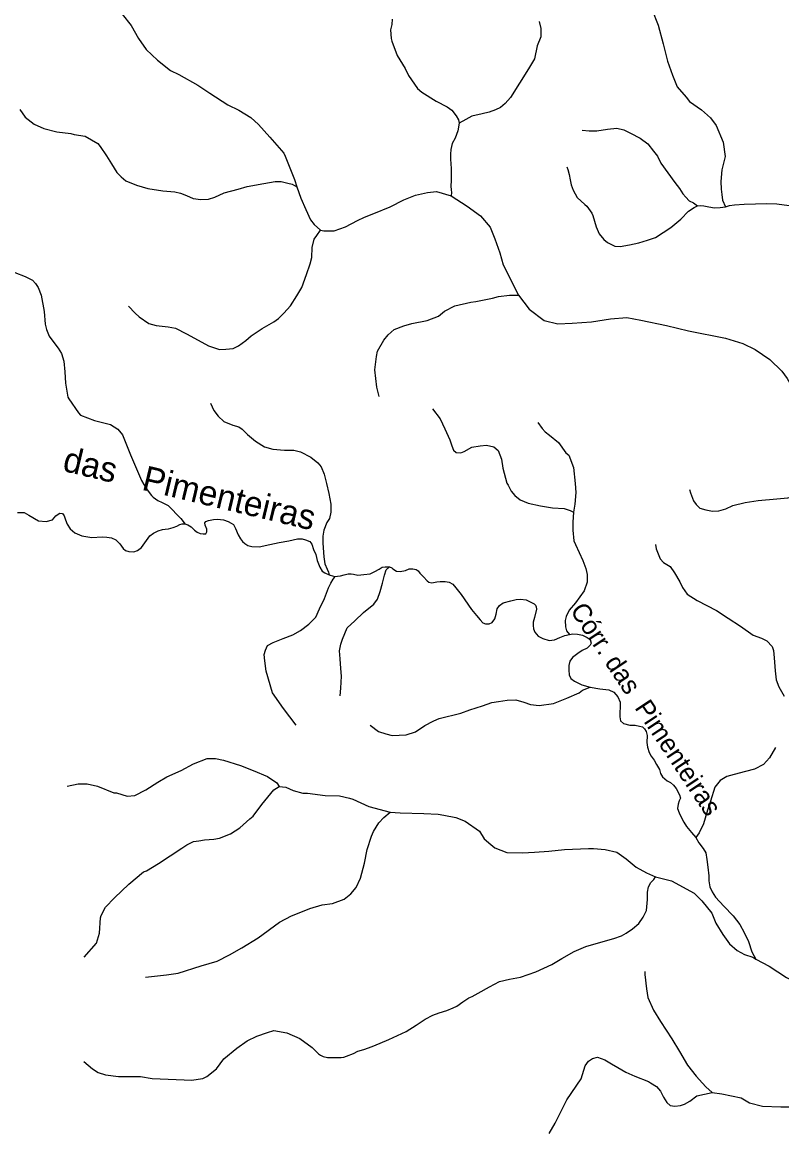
# Model space of a CAD drawing. Extents: x 436.3 to 500.4, y 8231 to 8286.4.
# Drawn here: x 478.01 to 484.1, y 8252.95 to 8261.84 of the extents above; entities that cross this region are included whole.
import ezdxf
from ezdxf.enums import TextEntityAlignment as Align

# ---------------------------------------------------------------- set-up
doc = ezdxf.new("R2010")
doc.units = 0
doc.header["$LTSCALE"] = 0.08
doc.linetypes.add('LONG_DASHED', pattern=[7.5, 6, -1.5])
doc.layers.add('61', color=7, linetype='Continuous')
doc.layers.add('9', color=7, linetype='LONG_DASHED', lineweight=25)

msp = doc.modelspace()

# ---------------------------------------------------------------- linework, layer by layer
at = {"layer": '9'}
for points in [[(478.8118, 8261.9018), (478.8826, 8261.8102), (478.9428, 8261.708), (479.003, 8261.6199), (479.0951, 8261.5319), (479.1978, 8261.4509), (479.2651, 8261.4193), (479.4186, 8261.333), (479.5142, 8261.2696), (479.6593, 8261.1746), (479.7478, 8261.1323), (479.8435, 8261.0724), (479.9036, 8261.0161), (479.9957, 8260.914), (480.109, 8260.7871), (480.1196, 8260.7624), (480.194, 8260.5757), (480.2117, 8260.5158)], [(483.0603, 8261.9419), (483.1111, 8261.8132), (483.1517, 8261.664), (483.1856, 8261.5251), (483.2262, 8261.4133), (483.2635, 8261.3185), (483.3357, 8261.2354), (483.3629, 8261.2015), (483.458, 8261.1338), (483.5294, 8261.0694), (483.577, 8261.0085), (483.6313, 8260.8763), (483.6482, 8260.7596), (483.6208, 8260.6545), (483.614, 8260.5596), (483.6173, 8260.4989), (483.6207, 8260.4549), (483.6275, 8260.4109), (483.6512, 8260.3567)], [(480.9782, 8261.8607), (480.9734, 8261.8184), (480.9623, 8261.7766), (480.9677, 8261.7071), (480.9733, 8261.6848), (481.0179, 8261.5706), (481.0821, 8261.4649), (481.1072, 8261.4093), (481.1798, 8261.3063), (481.2161, 8261.2757), (481.3305, 8261.2033), (481.417, 8261.1588), (481.4568, 8261.1321), (481.4903, 8261.0874), (481.5094, 8261.0546), (481.5132, 8261.0267)], [(482.1555, 8261.8443), (482.1702, 8261.7858), (482.1701, 8261.7201), (482.1407, 8261.647), (482.1186, 8261.5446), (482.0709, 8261.4643), (481.9274, 8261.2333), (481.8834, 8261.1858), (481.8466, 8261.1529), (481.8063, 8261.1346), (481.7549, 8261.1164), (481.6999, 8261.1017), (481.6156, 8261.0834), (481.5679, 8261.0579), (481.5132, 8261.0267)], [(477.9899, 8261.1367), (478.0328, 8261.0753), (478.1053, 8261.0198), (478.1815, 8260.9844), (478.2862, 8260.9586), (478.3981, 8260.9444), (478.4267, 8260.9374), (478.5148, 8260.9234), (478.6147, 8260.8643), (478.6338, 8260.8406), (478.6862, 8260.7649), (478.7243, 8260.7011), (478.7696, 8260.6325), (478.8036, 8260.5959), (478.8417, 8260.5652), (478.925, 8260.5298), (479.0178, 8260.5039), (479.1369, 8260.4851), (479.2343, 8260.4757), (479.278, 8260.4656), (479.328, 8260.4467), (479.3803, 8260.4231), (479.4422, 8260.4161), (479.504, 8260.4184), (479.554, 8260.435), (479.6301, 8260.4682), (479.7418, 8260.4968), (479.8132, 8260.5205), (479.9467, 8260.5448), (480.0394, 8260.559), (480.087, 8260.5591), (480.1393, 8260.5472), (480.175, 8260.5378), (480.2117, 8260.5158)], [(481.5132, 8261.0267), (481.5038, 8260.965), (481.4813, 8260.9072), (481.4588, 8260.8641), (481.4475, 8260.8157), (481.4456, 8260.7801), (481.4456, 8260.739), (481.4513, 8260.6644), (481.4491, 8260.5664), (481.4472, 8260.5217), (481.4492, 8260.4917), (481.4529, 8260.4712), (481.4492, 8260.445)], [(482.5003, 8260.9702), (482.5561, 8260.9654), (482.6192, 8260.9653), (482.7057, 8260.9793), (482.7805, 8260.9863), (482.8343, 8260.9747), (482.8881, 8260.9467), (482.9652, 8260.907), (483.0283, 8260.8605), (483.0727, 8260.8022), (483.1054, 8260.7626), (483.1334, 8260.7067), (483.1871, 8260.6298), (483.2432, 8260.5506), (483.2812, 8260.5037), (483.3093, 8260.4618), (483.3325, 8260.434), (483.3607, 8260.4058), (483.3935, 8260.3896), (483.4256, 8260.3655)], [(482.3786, 8260.6773), (482.3854, 8260.657), (482.3956, 8260.6163), (482.4058, 8260.5723), (482.4126, 8260.5316), (482.4296, 8260.491), (482.4602, 8260.43), (482.5214, 8260.3758), (482.5384, 8260.3622), (482.5792, 8260.3047), (482.586, 8260.2877), (482.6132, 8260.1962), (482.637, 8260.1387), (482.6744, 8260.0947), (482.705, 8260.071), (482.7628, 8260.0404), (482.807, 8260.037), (482.8818, 8260.0506), (482.9565, 8260.0675), (483.0245, 8260.0879), (483.0891, 8260.1115), (483.2114, 8260.1894), (483.293, 8260.2572), (483.3542, 8260.3215), (483.3985, 8260.352), (483.4256, 8260.3655)], [(480.2117, 8260.5158), (480.2449, 8260.4253), (480.2839, 8260.3337), (480.3229, 8260.2526), (480.3512, 8260.2139), (480.4009, 8260.1693)], [(480.4009, 8260.1693), (480.4295, 8260.1647), (480.5108, 8260.1647), (480.6029, 8260.1965), (480.6983, 8260.2458), (480.7549, 8260.2741), (480.8292, 8260.3022), (480.96, 8260.3551), (481.0696, 8260.4115), (481.1651, 8260.4503), (481.2606, 8260.4715), (481.3313, 8260.4785), (481.4492, 8260.445)], [(481.4492, 8260.445), (481.5788, 8260.3622), (481.6849, 8260.2847), (481.7627, 8260.1931), (481.7996, 8260.1006), (481.8416, 8259.9871), (481.8676, 8259.8904), (481.9907, 8259.6476)], [(483.4256, 8260.3655), (483.4481, 8260.3678), (483.4781, 8260.3651), (483.5176, 8260.3557), (483.5639, 8260.3489), (483.6088, 8260.3502), (483.6512, 8260.3567)], [(483.6512, 8260.3567), (483.6838, 8260.3666), (483.7219, 8260.372), (483.7996, 8260.3788), (483.9833, 8260.3828), (484.0638, 8260.3802), (484.1606, 8260.3667)], [(478.8615, 8259.56), (478.916, 8259.5022), (478.9472, 8259.4752), (479.025, 8259.4211), (479.0833, 8259.4057), (479.1805, 8259.3943), (479.2387, 8259.3828), (479.3281, 8259.3365), (479.4215, 8259.2863), (479.5032, 8259.2401), (479.5926, 8259.2131), (479.643, 8259.2132), (479.7013, 8259.221), (479.7439, 8259.2404), (479.8021, 8259.2829), (479.8448, 8259.3215), (479.934, 8259.3796), (480.0271, 8259.4338), (480.0659, 8259.4609), (480.1084, 8259.5034), (480.1627, 8259.5614), (480.213, 8259.6425), (480.2517, 8259.7082), (480.2904, 8259.8126), (480.3181, 8259.8994), (480.3335, 8259.9497), (480.3354, 8260.0294), (480.3517, 8260.0957), (480.3722, 8260.1273), (480.4009, 8260.1693)], [(477.9497, 8259.8287), (478.034, 8259.7967), (478.0923, 8259.7678), (478.115, 8259.7421), (478.1378, 8259.7099), (478.1605, 8259.6488), (478.1866, 8259.5169), (478.1937, 8259.4148), (478.2035, 8259.373), (478.2262, 8259.3183), (478.2619, 8259.2669), (478.2977, 8259.2219), (478.3236, 8259.18), (478.3432, 8259.1189), (478.3499, 8259.0321), (478.3565, 8258.9419), (478.3762, 8258.8294), (478.3827, 8258.8165), (478.4607, 8258.704), (478.4769, 8258.6846), (478.5904, 8258.643), (478.7167, 8258.611), (478.7751, 8258.5724), (478.814, 8258.5274), (478.8773, 8258.3678), (478.9652, 8258.162), (479.0042, 8258.0977), (479.0465, 8258.0398), (479.06, 8258.0262), (479.0963, 8258.0017), (479.1328, 8257.9837), (479.1535, 8257.9746), (479.1795, 8257.9605), (479.2133, 8257.9283), (479.2483, 8257.8884), (479.2822, 8257.8549), (479.3017, 8257.8331), (479.3149, 8257.8127)], [(480.8723, 8258.836), (480.8549, 8258.9095), (480.8372, 8259.0478), (480.85, 8259.1558), (480.8586, 8259.1991), (480.9106, 8259.2855), (480.9452, 8259.3288), (480.9928, 8259.372), (481.0709, 8259.4023), (481.136, 8259.4196), (481.2574, 8259.4455), (481.3484, 8259.4801), (481.3962, 8259.519), (481.4785, 8259.5622), (481.6086, 8259.5926), (481.6476, 8259.5969), (481.782, 8259.6228), (481.8298, 8259.6357), (481.9169, 8259.6486), (481.9907, 8259.6476)], [(481.9907, 8259.6476), (482.0749, 8259.5359), (482.1958, 8259.4436), (482.3057, 8259.4173), (482.4206, 8259.4226), (482.576, 8259.4332), (482.728, 8259.4578), (482.8587, 8259.4684), (482.9719, 8259.4473), (483.1771, 8259.405), (483.354, 8259.3628), (483.6512, 8259.3031), (483.7893, 8259.2609), (483.8886, 8259.2118), (484.0056, 8259.1308), (484.1034, 8259.0383), (484.1461, 8258.9784), (484.2137, 8258.8624), (484.2635, 8258.7639), (484.349, 8258.5669), (484.3882, 8258.4578), (484.4632, 8258.2467), (484.531, 8258.0902), (484.5562, 8258.0303)], [(479.521, 8258.7805), (479.5462, 8258.7232), (479.5824, 8258.6767), (479.6257, 8258.6336), (479.6978, 8258.6051), (479.7483, 8258.5908), (479.7736, 8258.5729), (479.8169, 8258.5299), (479.8818, 8258.4762), (479.954, 8258.4297), (480.0188, 8258.4119), (480.1125, 8258.4048), (480.1881, 8258.4048), (480.2421, 8258.3905), (480.325, 8258.3476), (480.3818, 8258.3014), (480.4072, 8258.2715), (480.4305, 8258.2118), (480.4492, 8258.1381), (480.4679, 8258.0576), (480.4843, 8257.9703), (480.4844, 8257.9058), (480.4738, 8257.8567), (480.4535, 8257.8241), (480.429, 8257.7631), (480.421, 8257.7142), (480.4212, 8257.6571), (480.4296, 8257.5472), (480.4372, 8257.4925), (480.4552, 8257.4488), (480.4653, 8257.4249), (480.4718, 8257.4051)], [(481.3004, 8258.7355), (481.3624, 8258.6569), (481.4004, 8258.5747), (481.4384, 8258.4858), (481.4557, 8258.4378), (481.4695, 8258.4036), (481.4901, 8258.3866), (481.5279, 8258.3831), (481.5554, 8258.3934), (481.6172, 8258.4277), (481.6823, 8258.4379), (481.7339, 8258.4448), (481.7923, 8258.4311), (481.8267, 8258.4003), (481.8543, 8258.3319), (481.8648, 8258.26), (481.896, 8258.1402), (481.9063, 8258.1232), (481.9305, 8258.0752), (481.9615, 8258.041), (482.0028, 8258.0068), (482.0681, 8257.9794), (482.1677, 8257.9589), (482.264, 8257.9419), (482.3567, 8257.935), (482.4049, 8257.9214), (482.4303, 8257.9061)], [(482.1459, 8258.6265), (482.1804, 8258.5787), (482.2045, 8258.5512), (482.2389, 8258.5239), (482.3112, 8258.4657), (482.3697, 8258.3837), (482.3939, 8258.3631), (482.4319, 8258.2639), (482.4459, 8258.1373), (482.4495, 8258.0655), (482.443, 8257.9713), (482.4303, 8257.9061)], [(483.3616, 8258.0878), (483.37, 8258.0627), (483.3954, 8257.9985), (483.4151, 8257.9679), (483.446, 8257.94), (483.4937, 8257.9261), (483.5469, 8257.9149), (483.5975, 8257.9178), (483.6535, 8257.9346), (483.7094, 8257.9597), (483.8075, 8257.9849), (483.914, 8258.0017), (484.0625, 8258.013), (484.1523, 8258.0215), (484.228, 8258.0439), (484.2869, 8258.0607), (484.3345, 8258.0719), (484.3878, 8258.0748), (484.4299, 8258.0748), (484.472, 8258.0665), (484.5085, 8258.0554), (484.5562, 8258.0303)], [(477.9721, 8257.9042), (478.0262, 8257.9043), (478.0624, 8257.882), (478.1391, 8257.8373), (478.2023, 8257.8329), (478.2518, 8257.8464), (478.2787, 8257.8777), (478.2967, 8257.8912), (478.3107, 8257.8989), (478.3318, 8257.8967), (478.3459, 8257.8781), (478.3553, 8257.8456), (478.3693, 8257.8108), (478.3951, 8257.7738), (478.4326, 8257.7414), (478.4862, 8257.7182), (478.568, 8257.7045), (478.6519, 8257.7091), (478.6869, 8257.7069), (478.7243, 8257.6999), (478.7616, 8257.6837), (478.7921, 8257.6536), (478.8202, 8257.6166), (478.8365, 8257.598), (478.8646, 8257.5911), (478.9042, 8257.5888), (478.9345, 8257.6004), (478.9671, 8257.6237), (478.9927, 8257.6609), (479.034, 8257.7164), (479.0622, 8257.7382), (479.1005, 8257.7562), (479.1344, 8257.7675), (479.157, 8257.7699), (479.184, 8257.7721), (479.2202, 8257.7834), (479.2495, 8257.7946), (479.2743, 8257.8081), (479.2924, 8257.8127), (479.3149, 8257.8127)], [(482.4303, 8257.9061), (482.4262, 8257.8275), (482.4263, 8257.7625), (482.4335, 8257.6769), (482.4472, 8257.6461), (482.5059, 8257.5194), (482.5302, 8257.4544), (482.5406, 8257.4065), (482.5407, 8257.3449), (482.5168, 8257.2764), (482.4483, 8257.1805), (482.3969, 8257.12), (482.3729, 8257.0685), (482.3661, 8257.0377), (482.3662, 8256.9863), (482.3766, 8256.9555), (482.3997, 8256.9245)], [(479.3149, 8257.8127), (479.3376, 8257.806), (479.3647, 8257.7902), (479.3919, 8257.7633), (479.4123, 8257.7454), (479.4372, 8257.7364), (479.462, 8257.7342), (479.4823, 8257.7342), (479.4913, 8257.7477), (479.4912, 8257.7702), (479.4776, 8257.8038), (479.4753, 8257.8219), (479.4821, 8257.833), (479.5046, 8257.8398), (479.543, 8257.8489), (479.5745, 8257.8511), (479.6242, 8257.8444), (479.6627, 8257.8332), (479.6853, 8257.8198), (479.7034, 8257.8085), (479.7215, 8257.7771), (479.742, 8257.7255), (479.7601, 8257.6918), (479.776, 8257.6716), (479.7942, 8257.6559), (479.819, 8257.6401), (479.8506, 8257.6312), (479.9093, 8257.629), (479.995, 8257.6471), (480.0717, 8257.6629), (480.1474, 8257.6781), (480.2173, 8257.6916), (480.2557, 8257.6916), (480.2806, 8257.685), (480.3166, 8257.6715), (480.3325, 8257.6491), (480.3462, 8257.6086), (480.3643, 8257.5659), (480.3758, 8257.5187), (480.3962, 8257.4648), (480.4166, 8257.4333), (480.4376, 8257.4196), (480.4718, 8257.4051)], [(483.0906, 8257.6479), (483.094, 8257.612), (483.127, 8257.5336), (483.1533, 8257.5042), (483.2059, 8257.4715), (483.2421, 8257.4192), (483.285, 8257.3473), (483.3048, 8257.3015), (483.3443, 8257.2492), (483.4232, 8257.197), (483.5777, 8257.1186), (483.6731, 8257.0565), (483.7717, 8256.9912), (483.8737, 8256.9194), (483.9394, 8256.8965), (483.9825, 8256.8755), (484.0253, 8256.8297), (484.0352, 8256.7971), (484.0419, 8256.7382), (484.0487, 8256.6334), (484.0586, 8256.5614), (484.0784, 8256.5057), (484.1212, 8256.4305)], [(480.518, 8257.39), (480.5381, 8257.3923), (480.5618, 8257.3949), (480.5932, 8257.4039), (480.6248, 8257.4129), (480.6473, 8257.4129), (480.6676, 8257.4107), (480.7016, 8257.4016), (480.7493, 8257.4061), (480.8012, 8257.4129), (480.8373, 8257.4308), (480.8732, 8257.4488), (480.8958, 8257.4646), (480.9206, 8257.4691), (480.9567, 8257.4691)], [(480.5602, 8256.4333), (480.5651, 8256.4946), (480.57, 8256.5914), (480.5648, 8256.6527), (480.5595, 8256.7292), (480.5542, 8256.7955), (480.5643, 8256.8465), (480.5795, 8256.8873), (480.6151, 8256.9792), (480.6763, 8257.0352), (480.7477, 8257.1016), (480.8294, 8257.1679), (480.86, 8257.2086), (480.8803, 8257.2698), (480.9005, 8257.3361), (480.9157, 8257.4023), (480.9296, 8257.4429), (480.9567, 8257.4691)], [(480.9567, 8257.4691), (480.9747, 8257.4601), (480.9815, 8257.4512), (481.0108, 8257.4332), (481.0424, 8257.4309), (481.0829, 8257.4377), (481.1145, 8257.4512), (481.1438, 8257.4512), (481.1686, 8257.4467), (481.1867, 8257.4355), (481.2002, 8257.4175), (481.2274, 8257.3883), (481.2568, 8257.3546), (481.2703, 8257.3456), (481.2951, 8257.3411), (481.3357, 8257.3479), (481.3627, 8257.3501), (481.4032, 8257.3501), (481.4348, 8257.3456), (481.4641, 8257.33), (481.4868, 8257.3008), (481.5297, 8257.2468), (481.6141, 8257.1266), (481.6525, 8257.0772), (481.6819, 8257.0435), (481.7045, 8257.0188), (481.7248, 8257.0098), (481.7563, 8257.0121), (481.7789, 8257.0211), (481.8013, 8257.0503), (481.8125, 8257.0886), (481.8192, 8257.1313), (481.8372, 8257.1583), (481.8687, 8257.1807), (481.9295, 8257.1942), (481.9723, 8257.2055), (482.0061, 8257.21), (482.0512, 8257.2032), (482.0941, 8257.1831), (482.1166, 8257.1718), (482.1279, 8257.1606), (482.1325, 8257.1471), (482.1347, 8257.1291), (482.1177, 8257.0615), (482.1087, 8257.0256), (482.1088, 8256.9964), (482.1111, 8256.9716), (482.1202, 8256.9446), (482.1495, 8256.9132), (482.1856, 8256.893), (482.2353, 8256.8772), (482.2781, 8256.8817), (482.3209, 8256.902), (482.3614, 8256.9178), (482.3997, 8256.9245)], [(480.2077, 8256.1984), (480.1051, 8256.331), (480.0179, 8256.4585), (479.9663, 8256.632), (479.9558, 8256.7135), (479.9506, 8256.7646), (479.9607, 8256.8003), (479.976, 8256.836), (480.022, 8256.8615), (480.1038, 8256.8921), (480.1804, 8256.9228), (480.2418, 8256.9585), (480.3082, 8257.0096), (480.3642, 8257.0657), (480.3947, 8257.132), (480.4354, 8257.2135), (480.4659, 8257.3003), (480.4843, 8257.3367), (480.5032, 8257.3687), (480.5141, 8257.383), (480.518, 8257.39)], [(480.4718, 8257.4051), (480.4797, 8257.4017), (480.4986, 8257.3949), (480.518, 8257.39)], [(482.3997, 8256.9245), (482.4268, 8256.9313), (482.4629, 8256.929), (482.5035, 8256.9201), (482.5418, 8256.9021), (482.5643, 8256.8842), (482.5735, 8256.8571), (482.5644, 8256.8391), (482.542, 8256.8145), (482.5014, 8256.7964), (482.4677, 8256.7739), (482.4226, 8256.7401), (482.4024, 8256.7109), (482.3934, 8256.6772), (482.3935, 8256.6389), (482.3982, 8256.6016), (482.4095, 8256.5723), (482.4388, 8256.5499), (482.4998, 8256.5229), (482.5652, 8256.5027)], [(480.8014, 8256.1985), (480.8679, 8256.1478), (480.925, 8256.1289), (480.9757, 8256.1163), (481.0896, 8256.1195), (481.1655, 8256.1448), (481.2383, 8256.1954), (481.3046, 8256.2302), (481.3363, 8256.2429), (481.3553, 8256.2524), (481.5269, 8256.2936), (481.5997, 8256.3221), (481.7009, 8256.3537), (481.7769, 8256.3791), (481.8306, 8256.3886), (481.9003, 8256.3982), (481.9699, 8256.4013), (482.0333, 8256.3823), (482.0872, 8256.3634), (482.1568, 8256.3571), (482.2708, 8256.373), (482.3784, 8256.4142), (482.4765, 8256.4585), (482.5049, 8256.4775), (482.5652, 8256.5027)], [(482.5652, 8256.5027), (482.6419, 8256.4892), (482.7163, 8256.4803), (482.7546, 8256.4623), (482.7884, 8256.4263), (482.8066, 8256.3836), (482.8066, 8256.3386), (482.8022, 8256.3025), (482.8022, 8256.2643), (482.809, 8256.2328), (482.8316, 8256.2125), (482.8834, 8256.1991), (482.9263, 8256.1991), (482.9624, 8256.1901), (482.9849, 8256.1835), (483.0007, 8256.1677), (483.0142, 8256.1474), (483.0217, 8256.1147), (483.0195, 8256.0585), (483.024, 8256.0202), (483.0376, 8255.9774), (483.0534, 8255.9504), (483.0782, 8255.9167), (483.0985, 8255.8829), (483.1211, 8255.8424), (483.1302, 8255.8109), (483.146, 8255.7838), (483.1843, 8255.7524), (483.2091, 8255.7389), (483.2339, 8255.7164), (483.2543, 8255.6893), (483.2813, 8255.6399), (483.289, 8255.6113), (483.2799, 8255.5909), (483.2709, 8255.5639), (483.2664, 8255.5301), (483.2799, 8255.4941), (483.298, 8255.4558), (483.316, 8255.4197), (483.3386, 8255.3859), (483.3792, 8255.3364), (483.413, 8255.2981)], [(484.0523, 8256.0196), (484.0043, 8255.9356), (483.9561, 8255.8816), (483.8841, 8255.8455), (483.8119, 8255.8274), (483.7218, 8255.8032), (483.6617, 8255.7852), (483.6076, 8255.7551), (483.5656, 8255.701), (483.5296, 8255.5871), (483.5056, 8255.515), (483.4755, 8255.407), (483.4394, 8255.3349), (483.413, 8255.2981)], [(478.3703, 8255.7088), (478.459, 8255.7266), (478.5301, 8255.7267), (478.6145, 8255.709), (478.7433, 8255.656), (478.7655, 8255.6561), (478.8499, 8255.6295), (478.912, 8255.6341), (479.0007, 8255.6784), (479.0984, 8255.7404), (479.1692, 8255.7847), (479.2846, 8255.8335), (479.3821, 8255.8866), (479.4931, 8255.931), (479.5608, 8255.9309), (479.6229, 8255.9176), (479.7604, 8255.8735), (479.8625, 8255.8338), (479.9777, 8255.7852), (480.0531, 8255.7366), (480.0708, 8255.7059)], [(478.5066, 8254.3358), (478.6064, 8254.4491), (478.6286, 8254.5288), (478.6374, 8254.653), (478.6419, 8254.6707), (478.6773, 8254.7372), (478.7483, 8254.8125), (478.8635, 8254.9233), (478.9833, 8255.0208), (479.0055, 8255.0298), (479.1031, 8255.0874), (479.1962, 8255.1494), (479.2894, 8255.2114), (479.3293, 8255.2381), (479.3825, 8255.2646), (479.4269, 8255.2692), (479.4713, 8255.278), (479.5466, 8255.2825), (479.5909, 8255.2914), (479.6796, 8255.3269), (479.7549, 8255.3756), (479.8348, 8255.4465), (479.8613, 8255.4686), (479.9322, 8255.5617), (480.0265, 8255.6794), (480.0708, 8255.7059)], [(480.0708, 8255.7059), (480.124, 8255.7012), (480.1817, 8255.6746), (480.2614, 8255.6526), (480.2976, 8255.6526), (480.4394, 8255.6349), (480.5544, 8255.6306), (480.6342, 8255.6129), (480.6607, 8255.604), (480.7891, 8255.5465), (480.9609, 8255.4995)], [(478.9984, 8254.1751), (479.1666, 8254.1961), (479.259, 8254.2087), (479.444, 8254.2676), (479.5742, 8254.3055), (479.6709, 8254.356), (479.7716, 8254.4107), (479.9019, 8254.4906), (480.0741, 8254.6167), (480.1707, 8254.6672), (480.2714, 8254.7092), (480.3176, 8254.7261), (480.4154, 8254.756), (480.4994, 8254.7686), (480.5918, 8254.8023), (480.6464, 8254.8443), (480.6882, 8254.8947), (480.7218, 8254.9704), (480.7554, 8255.0922), (480.7764, 8255.2013), (480.81, 8255.3064), (480.8268, 8255.3441), (480.8687, 8255.4155), (480.9106, 8255.4574), (480.9609, 8255.4995)], [(480.9609, 8255.4995), (481.0415, 8255.4934), (481.2317, 8255.4891), (481.3468, 8255.4847), (481.391, 8255.4759), (481.4884, 8255.4582), (481.5636, 8255.4272), (481.6787, 8255.3476), (481.7141, 8255.2856), (481.7697, 8255.2396), (481.8007, 8255.213), (481.898, 8255.1777), (482.022, 8255.1733), (482.1193, 8255.1778), (482.2344, 8255.1867), (482.3584, 8255.2001), (482.5531, 8255.2091), (482.5929, 8255.2091), (482.686, 8255.2003), (482.7789, 8255.1782), (482.8542, 8255.1252), (482.9338, 8255.0588), (483.018, 8255.0146), (483.0886, 8254.981)], [(483.413, 8255.2981), (483.4378, 8255.2531), (483.4716, 8255.208), (483.4922, 8255.1729), (483.5012, 8255.1211), (483.5102, 8255.058), (483.5169, 8254.9903), (483.5169, 8254.9498), (483.5259, 8254.9001), (483.5439, 8254.8596), (483.5709, 8254.819), (483.6363, 8254.7469), (483.7129, 8254.668), (483.7652, 8254.599), (483.8012, 8254.5358), (483.835, 8254.4636), (483.8619, 8254.3802), (483.8935, 8254.3215)], [(478.5034, 8253.5002), (478.5732, 8253.4414), (478.6173, 8253.412), (478.6761, 8253.3936), (478.7826, 8253.3788), (478.9588, 8253.3788), (479.0507, 8253.3641), (479.3076, 8253.353), (479.3663, 8253.3493), (479.4581, 8253.3641), (479.4911, 8253.3787), (479.5682, 8253.4412), (479.627, 8253.5221), (479.7297, 8253.6067), (479.8141, 8253.6656), (479.8912, 8253.7024), (479.9771, 8253.733), (480.0284, 8253.7477), (480.1311, 8253.7294), (480.2375, 8253.6852), (480.3365, 8253.6118), (480.3864, 8253.5602), (480.4028, 8253.5496), (480.4229, 8253.5402), (480.4594, 8253.533), (480.4984, 8253.5319), (480.5432, 8253.5331), (480.569, 8253.5331), (480.5891, 8253.5355), (480.6115, 8253.5437), (480.6669, 8253.565), (480.7004, 8253.5817), (480.7498, 8253.596), (480.817, 8253.6196), (480.8807, 8253.6457), (480.9514, 8253.6753), (481.0888, 8253.7391), (481.1698, 8253.7908), (481.2415, 8253.8387), (481.304, 8253.8701), (481.3536, 8253.8904), (481.4143, 8253.9089), (481.4657, 8253.9292), (481.497, 8253.944), (481.543, 8253.979), (481.5926, 8254.0105), (481.6183, 8254.0215), (481.6662, 8254.0473), (481.7581, 8254.099), (481.8381, 8254.1421), (481.9189, 8254.1606), (482.0071, 8254.1754), (482.1303, 8254.2178), (482.259, 8254.2788), (482.337, 8254.3257), (482.4362, 8254.381), (482.5319, 8254.4216), (482.633, 8254.4512), (482.7563, 8254.4863), (482.816, 8254.5088), (482.8546, 8254.529), (482.9062, 8254.5641), (482.9558, 8254.6065), (482.9908, 8254.658), (483.0184, 8254.7114), (483.0259, 8254.7998), (483.0241, 8254.8577), (483.0333, 8254.8999), (483.0518, 8254.9368), (483.0757, 8254.9608), (483.0886, 8254.981)], [(483.0886, 8254.981), (483.2174, 8254.948), (483.4004, 8254.8499), (483.4624, 8254.7879), (483.542, 8254.6905), (483.573, 8254.6108), (483.6305, 8254.5177), (483.6836, 8254.4424), (483.7456, 8254.3893), (483.8032, 8254.3583), (483.8696, 8254.3363), (483.8935, 8254.3215)], [(483.8935, 8254.3215), (484.0025, 8254.2654), (484.1398, 8254.1725), (484.255, 8254.1149), (484.3275, 8254.0687), (484.3674, 8254.0066), (484.3983, 8253.949), (484.4292, 8253.8559), (484.4513, 8253.8336), (484.5398, 8253.745), (484.7082, 8253.6208), (484.7215, 8253.6119), (484.8101, 8253.5188), (484.872, 8253.4389), (484.9296, 8253.3679), (484.965, 8253.3279), (485.0083, 8253.2985)], [(483.0038, 8254.2228), (483.0038, 8254.1973), (483.0163, 8254.0827), (483.0289, 8254.0126), (483.0734, 8253.9106), (483.1305, 8253.8215), (483.2193, 8253.6814), (483.2828, 8253.5794), (483.3463, 8253.471), (483.4155, 8253.3817), (483.4658, 8253.3266), (483.4921, 8253.2954), (483.5447, 8253.2522)], [(482.2363, 8252.9218), (482.2835, 8253.006), (482.3787, 8253.1923), (482.4941, 8253.3607), (482.5256, 8253.466), (482.5519, 8253.5027), (482.5833, 8253.5238), (482.6252, 8253.5344), (482.6828, 8253.5134), (482.7352, 8253.4819), (482.7882, 8253.4504), (482.8509, 8253.4136), (482.9243, 8253.3821), (483.0343, 8253.3402), (483.05, 8253.3297), (483.0972, 8253.2982), (483.1285, 8253.2614), (483.1547, 8253.2141), (483.1808, 8253.1721), (483.207, 8253.1458), (483.2437, 8253.1405), (483.2908, 8253.1459), (483.3223, 8253.1565), (483.3643, 8253.1828), (483.4221, 8253.225), (483.5447, 8253.2522)], [(483.5447, 8253.2522), (483.6213, 8253.2409), (483.7755, 8253.2092), (483.8436, 8253.1672), (483.9485, 8253.141), (484.0954, 8253.1358), (484.2057, 8253.1359), (484.2792, 8253.1518), (484.3529, 8253.2202), (484.4213, 8253.2886), (484.5053, 8253.315), (484.6051, 8253.3203), (484.7077, 8253.2792), (484.7742, 8253.268)]]:
    msp.add_lwpolyline(points, dxfattribs=at)

# ---------------------------------------------------------------- texts
at = {"layer": '61'}
msp.add_text('Córrego          das   Pimenteiras', height=0.2, rotation=346.559, dxfattribs=at).set_placement((478.4981, 8258.1985), align=Align.CENTER)
msp.add_text('Córr. das  Pimenteiras', height=0.15, rotation=303.559, dxfattribs=at).set_placement((482.3999, 8257.1182))

doc.saveas('drawing.dxf')
